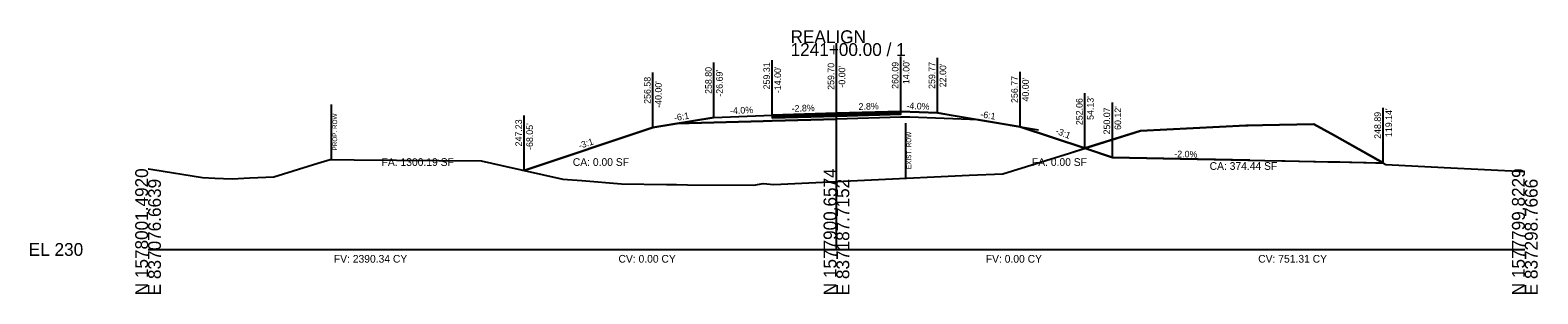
# Model space of a CAD drawing. Extents: x -26 to 6303, y -16 to 9563.
# Drawn here: x 1974.3 to 2302.8, y 990.3 to 1047.8 of the extents above; entities that cross this region are included whole.
import ezdxf

# ---------------------------------------------------------------- set-up
doc = ezdxf.new("R2010")
doc.units = 0
for name, color, linetype in [('ASPHALT_19MM1', 7, 'Continuous'), ('ASPHALT_9_5MM1', 7, 'Continuous'), ('CONST_DCH', 7, 'Continuous'), ('CONST_LV3', 7, 'Continuous'), ('Draft_XS_Grid', 7, 'Continuous'), ('DTM_P_FINISHED_GRADE2', 7, 'Continuous'), ('DTM_TEMP_DROP', 7, 'Continuous'), ('DTM_X_GROUND', 7, 'Continuous'), ('TRANS_EOP_PAVED', 7, 'Continuous'), ('TRANS_PAVED_SHOULDERS', 7, 'Continuous'), ('XS_CELL', 7, 'Continuous'), ('XS_M_SHAPES_EARTHWORK', 7, 'Continuous'), ('XS_P_ASPHALT', 7, 'Continuous'), ('XS_P_GROUND', 7, 'Continuous'), ('XS_P_ROW', 7, 'Continuous'), ('XS_P_SHOULDER', 7, 'Continuous'), ('XS_P_SUBGRADE_GRANULAR', 7, 'Continuous'), ('XS_P_TX_CLEARZONE', 7, 'Continuous'), ('XS_P_TX_FS_BS', 7, 'Continuous'), ('XS_SHEET_EW_TX_AREA', 7, 'Continuous'), ('XS_SHEET_EW_TX_VOLUME', 7, 'Continuous'), ('XS_X_ROW', 7, 'Continuous')]:
    doc.layers.add(name, color=color, linetype=linetype)

msp = doc.modelspace()

# ---------------------------------------------------------------- linework, layer by layer
at = {"layer": 'ASPHALT_19MM1'}
msp.add_lwpolyline([(2136, 1028.98), (2136, 1028.71), (2150, 1029.1), (2150, 1029.1), (2164, 1029.49), (2164, 1029.49), (2164, 1029.76), (2164, 1029.76), (2164, 1029.76), (2150, 1029.37), (2150, 1029.37), (2136, 1028.98), (2136, 1028.98)], dxfattribs=at)
at = {"layer": 'ASPHALT_9_5MM1'}
msp.add_lwpolyline([(2136, 1029.31), (2136, 1029.19), (2150, 1029.58), (2150, 1029.58), (2164, 1029.97), (2164, 1029.97), (2164, 1030.09), (2164, 1030.09), (2164, 1030.09), (2150, 1029.7), (2150, 1029.7), (2136, 1029.31), (2136, 1029.31)], dxfattribs=at)
at = {"layer": 'CONST_LV3'}
for points in [[(2150, 1029.7), (2150, 1029.7), (2162.93, 1030.06), (2162.93, 1030.06), (2162.93, 1030.06), (2163.57, 1030.08), (2163.57, 1030.08), (2164, 1030.09)], [(2172, 1029.77), (2172, 1029.77), (2165.96, 1030.01), (2165.96, 1030.01), (2165.96, 1030.01), (2164, 1030.09), (2164, 1030.09)], [(2115.24, 1027.46), (2110, 1026.58)], [(2180.96, 1028.28), (2194, 1026.11)]]:
    msp.add_lwpolyline(points, dxfattribs=at)
at = {"layer": 'DTM_P_FINISHED_GRADE2'}
msp.add_lwpolyline([(2081.95, 1017.23), (2110, 1026.58), (2123.31, 1028.8), (2136, 1029.31), (2150, 1029.7), (2164, 1030.09), (2172, 1029.77)], dxfattribs=at)
at = {"layer": 'DTM_X_GROUND'}
msp.add_lwpolyline([(2000, 1017.57), (2000.08, 1017.57), (2001.07, 1017.42), (2011.89, 1015.69), (2014.57, 1015.57), (2018.35, 1015.43), (2022.21, 1015.62), (2027.38, 1015.86), (2036.99, 1018.81), (2039.65, 1019.59), (2044.91, 1019.55), (2072.55, 1019.31), (2077.09, 1018.33), (2090.36, 1015.32), (2094.51, 1015.05), (2103.14, 1014.33), (2112.96, 1014.17), (2115.18, 1014.15), (2117.52, 1014.12), (2132.02, 1014), (2134.06, 1014.42), (2136.33, 1014.15), (2178.92, 1016.21), (2186.26, 1016.47), (2200.82, 1021.03), (2216.25, 1025.88), (2239.21, 1027.03), (2239.74, 1027.06), (2242.84, 1027.12), (2254, 1027.35), (2258.51, 1024.83), (2269.73, 1018.56), (2282.46, 1017.89), (2300, 1016.97)], dxfattribs=at)
at = {"layer": 'TRANS_PAVED_SHOULDERS'}
msp.add_lwpolyline([(2136, 1029.19), (2136, 1028.98), (2150, 1029.37), (2150, 1029.37), (2164, 1029.76), (2164, 1029.76), (2164, 1029.97), (2164, 1029.97), (2164, 1029.97), (2150, 1029.58), (2150, 1029.58), (2136, 1029.19), (2136, 1029.19)], dxfattribs=at)
at = {"layer": 'XS_CELL'}
for p, q in [((2150, 1000), (2150, 1045)), ((2000, 1000), (2150, 1000)), ((2150, 1000), (2300, 1000))]:
    msp.add_line(p, q, dxfattribs=at)
at = {"layer": 'XS_M_SHAPES_EARTHWORK'}
msp.add_lwpolyline([(2081.95, 1017.23), (2090.36, 1015.32), (2094.51, 1015.05), (2103.14, 1014.33), (2112.96, 1014.17), (2115.18, 1014.15), (2117.52, 1014.12), (2132.02, 1014), (2134.06, 1014.42), (2136.33, 1014.15), (2178.92, 1016.21), (2186.26, 1016.47), (2200.82, 1021.03), (2204.13, 1022.06), (2190, 1026.77), (2180.96, 1028.28), (2166, 1028.88), (2164, 1028.82), (2150, 1028.43), (2136, 1028.04), (2134, 1027.98), (2115.24, 1027.46), (2110, 1026.58)], close=True, dxfattribs=at)
at = {"layer": 'XS_P_GROUND'}
for points in [[(2123.31, 1028.8), (2110, 1026.58), (2081.95, 1017.23)], [(2172, 1029.77), (2190, 1026.77), (2204.13, 1022.06)], [(2210.12, 1020.07), (2190, 1026.77), (2190, 1026.77), (2190, 1026.77), (2175.2, 1029.24), (2175.2, 1029.24), (2172, 1029.77)], [(2240.09, 1019.47), (2210.12, 1020.07), (2210.12, 1020.07)], [(2240.09, 1019.47), (2243.33, 1019.4), (2247.75, 1019.31), (2257.1, 1019.13), (2257.75, 1019.11), (2259.68, 1019.08), (2267.44, 1018.92), (2269.14, 1018.89)]]:
    msp.add_lwpolyline(points, dxfattribs=at)
at = {"layer": 'XS_P_ROW'}
msp.add_line((2040, 1019.59), (2040, 1031.59), dxfattribs=at)
at = {"layer": 'XS_P_SHOULDER'}
for points in [[(2123.31, 1028.8), (2136, 1029.31), (2136, 1029.31)], [(2172, 1029.77), (2164, 1030.09), (2164, 1030.09)]]:
    msp.add_lwpolyline(points, dxfattribs=at)
at = {"layer": 'XS_P_SUBGRADE_GRANULAR'}
for points in [[(2136, 1028.04), (2150, 1028.43), (2150, 1028.43)], [(2164, 1028.82), (2164, 1028.82), (2150, 1028.43)], [(2180.96, 1028.28), (2166, 1028.88), (2166, 1028.88), (2166, 1028.88), (2164, 1028.82)], [(2115.24, 1027.46), (2134, 1027.98), (2134, 1027.98), (2136, 1028.04), (2136, 1028.04)]]:
    msp.add_lwpolyline(points, dxfattribs=at)
at = {"layer": 'XS_P_TX_CLEARZONE'}
for p, q in [((2150, 1029.7), (2150, 1041.7)), ((2164, 1030.09), (2164, 1042.09)), ((2172, 1029.77), (2172, 1041.77)), ((2172, 1029.77), (2172, 1041.77)), ((2110, 1026.58), (2110, 1038.58)), ((2123.31, 1028.8), (2123.31, 1040.8)), ((2136, 1029.31), (2136, 1041.31)), ((2190, 1026.77), (2190, 1038.77)), ((2204.13, 1022.06), (2204.13, 1034.06)), ((2210.12, 1020.07), (2210.12, 1032.07)), ((2081.95, 1017.23), (2081.95, 1029.23)), ((2269.14, 1018.89), (2269.14, 1030.89))]:
    msp.add_line(p, q, dxfattribs=at)
at = {"layer": 'XS_P_TX_FS_BS'}
msp.add_line((2210.12, 1020.07), (2269.14, 1018.89), dxfattribs=at)
msp.add_lwpolyline([(2269.14, 1018.89), (2258.51, 1024.83), (2254, 1027.35), (2242.84, 1027.12), (2239.74, 1027.06), (2239.21, 1027.03), (2216.25, 1025.88), (2204.13, 1022.06), (2210.12, 1020.07)], dxfattribs=at)
at = {"layer": 'XS_X_ROW'}
msp.add_line((2165.09, 1015.54), (2165.09, 1027.54), dxfattribs=at)

# ---------------------------------------------------------------- texts
at = {"layer": 'CONST_DCH'}
for p in [(2135.92, 1029.19), (2149.92, 1029.58), (2163.92, 1029.97), (2210.04, 1019.95)]:
    msp.add_text('X', height=0.24, dxfattribs=at).set_placement(p)
at = {"layer": 'CONST_LV3'}
msp.add_text('X', height=0.24, dxfattribs=at).set_placement((2109.92, 1026.46))
at = {"layer": 'Draft_XS_Grid'}
msp.add_text('-', height=0.0001, dxfattribs=at).set_placement((2000, 1000))
at = {"layer": 'DTM_TEMP_DROP'}
for p in [(2204.05, 1021.94), (2081.87, 1017.11)]:
    msp.add_text('X', height=0.24, dxfattribs=at).set_placement(p)
at = {"layer": 'TRANS_EOP_PAVED'}
for p in [(2171.92, 1029.65), (2189.92, 1026.65), (2204.05, 1021.94), (2081.87, 1017.11)]:
    msp.add_text('X', height=0.24, dxfattribs=at).set_placement(p)
at = {"layer": 'XS_CELL'}
for s, p in [('1241+00.00 / 1', (2140, 1042.2)), ('REALIGN', (2140, 1045)), ('EL 230', (1974, 998.6))]:
    msp.add_text(s, height=2.8, dxfattribs=at).set_placement(p)
for s, p in [('N 1578001.4920', (2000, 990)), ('E 837076.6639', (2002.8, 990)), ('N 1577900.6574', (2150, 990)), ('E 837187.7152', (2152.8, 990)), ('N 1577799.8229', (2300, 990)), ('E 837298.7666', (2302.8, 990))]:
    msp.add_text(s, height=2.8, rotation=90, dxfattribs=at).set_placement(p)
at = {"layer": 'XS_P_ASPHALT'}
msp.add_text('X', height=0.24, dxfattribs=at).set_placement((2269.06, 1018.77))
at = {"layer": 'XS_P_ROW'}
msp.add_text('PROP. ROW', height=1, rotation=90, dxfattribs=at).set_placement((2041.2, 1021.59))
at = {"layer": 'XS_P_SUBGRADE_GRANULAR'}
for p in [(2123.23, 1028.68), (2171.92, 1029.65)]:
    msp.add_text('X', height=0.24, dxfattribs=at).set_placement(p)
at = {"layer": 'XS_P_TX_CLEARZONE'}
for s, p in [('258.80', (2122.83, 1033.92)), ("-26.69'", (2125.23, 1033.32)), ('259.31', (2135.52, 1034.92)), ("-14.00'", (2137.92, 1034.1)), ('259.70', (2149.52, 1034.82)), ("-0.00'", (2151.92, 1035.31)), ('260.09', (2163.52, 1035.03)), ("14.00'", (2165.92, 1036.07)), ('259.77', (2171.52, 1035.02)), ("22.00'", (2173.92, 1035.38)), ('256.58', (2109.52, 1031.76)), ("-40.00'", (2111.92, 1030.9)), ('256.77', (2189.52, 1031.95)), ("40.00'", (2191.92, 1032.27)), ('252.06', (2203.65, 1027.12)), ("54.13'", (2206.05, 1028.26)), ('250.07', (2209.64, 1025.09)), ("60.12'", (2212.04, 1026.08)), ('248.89', (2268.66, 1024.12)), ("119.14'", (2271.06, 1024.52)), ('247.23', (2081.47, 1022.48)), ("-68.05'", (2083.87, 1021.71))]:
    msp.add_text(s, height=1.44, rotation=90, dxfattribs=at).set_placement(p)
at = {"layer": 'XS_P_TX_FS_BS'}
for s, rotation, p in [('-2.8%', 1.6039, (2140.25, 1030.03)), ('2.8%', 1.6039, (2154.84, 1030.44)), ('-4.0%', 357.7094, (2165.23, 1030.65)), ('-6:1', 9.4642, (2114.73, 1027.98)), ('-4.0%', 2.2906, (2126.84, 1029.54)), ('-6:1', 350.538, (2181.28, 1028.84)), ('-3:1', 338.2431, (2197.6, 1025.32)), ('-3:1', 18.4332, (2094.06, 1021.9)), ('-2.0%', 358.8542, (2223.61, 1020.13))]:
    msp.add_text(s, height=1.44, rotation=rotation, dxfattribs=at).set_placement(p)
at = {"layer": 'XS_SHEET_EW_TX_AREA'}
for s, p in [('FA: 1300.19 SF', (2050.89, 1018.22)), ('CA: 0.00 SF', (2092.56, 1018.22)), ('FA: 0.00 SF', (2192.6, 1018.22)), ('CA: 374.44 SF', (2231.32, 1017.36))]:
    msp.add_text(s, height=1.68, dxfattribs=at).set_placement(p)
at = {"layer": 'XS_SHEET_EW_TX_VOLUME'}
for s, p in [('FV: 2390.34 CY', (2040.49, 997.12)), ('CV: 0.00 CY', (2102.51, 997.12)), ('FV: 0.00 CY', (2182.55, 997.12)), ('CV: 751.31 CY', (2241.91, 997.12))]:
    msp.add_text(s, height=1.68, dxfattribs=at).set_placement(p)
at = {"layer": 'XS_X_ROW'}
msp.add_text('EXIST. ROW', height=1, rotation=90, dxfattribs=at).set_placement((2166.29, 1017.54))

doc.saveas('drawing.dxf')
